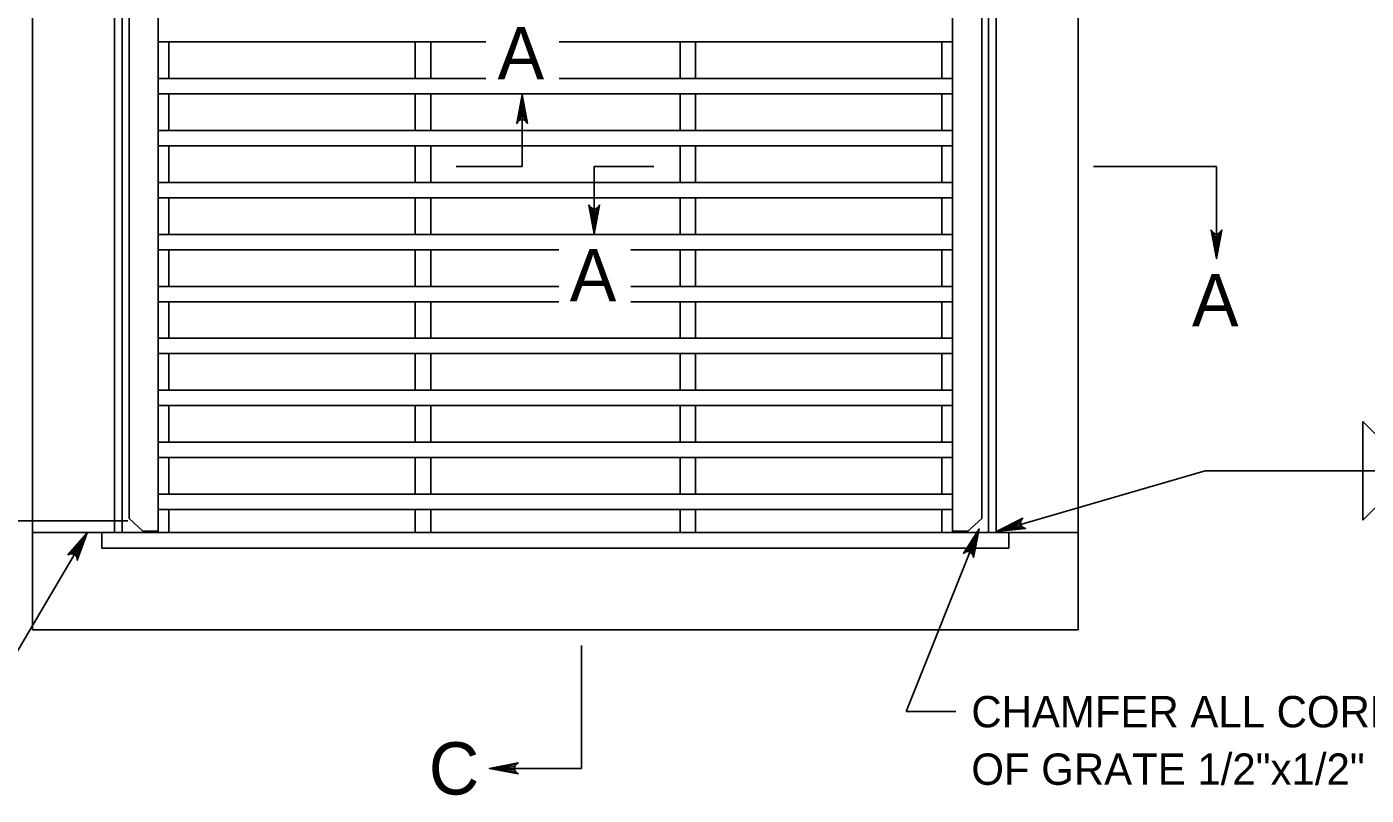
# Model space of a CAD drawing. Extents: x 0.7 to 7.67, y -7.49 to 2.47.
# Drawn here: x 3.543 to 6.105, y -4.567 to -3.097 of the extents above; entities that cross this region are included whole.
import ezdxf

# ---------------------------------------------------------------- set-up
doc = ezdxf.new("R2010")
doc.units = 0
for name, color, linetype in [('DETL-DIMS', 7, 'Continuous'), ('DETL-LINE', 7, 'Continuous'), ('DETL-NOTE', 7, 'Continuous'), ('DETL-TITL', 7, 'Continuous')]:
    doc.layers.add(name, color=color, linetype=linetype)

msp = doc.modelspace()

# ---------------------------------------------------------------- linework, layer by layer
at = {"layer": 'DETL-DIMS'}
for p, q in [((4.4903, -3.3641), (4.4903, -3.2269)), ((4.3644, -3.3641), (4.4903, -3.3641)), ((4.6283, -3.3641), (4.742, -3.3641)), ((4.6283, -3.3641), (4.6283, -3.4929)), ((5.5834, -3.3641), (5.8187, -3.3641)), ((5.8187, -3.3641), (5.8187, -3.5406)), ((5.7972, -3.9466), (5.3981, -4.0624)), ((5.7972, -3.9466), (5.9107, -3.9466)), ((3.7362, -4.0425), (3.0834, -4.0425)), ((3.4216, -4.4666), (3.6583, -4.0653)), ((5.2249, -4.4074), (5.3647, -4.0576)), ((4.6042, -4.2806), (4.6042, -4.5159)), ((5.3202, -4.4074), (5.2249, -4.4074)), ((4.6042, -4.5159), (4.4278, -4.5159))]:
    msp.add_line(p, q, dxfattribs=at)
for points in [[(4.4903, -3.2269), (4.5006, -3.2817), (4.4977, -3.2775), (4.494, -3.2753), (4.4903, -3.2747), (4.4866, -3.2753), (4.4829, -3.2775), (4.48, -3.2817), (4.4903, -3.2269), (4.4829, -3.2775), (4.4866, -3.2753), (4.4903, -3.2269), (4.4903, -3.2747), (4.494, -3.2753), (4.4903, -3.2269), (4.4977, -3.2775)], [(4.6283, -3.4929), (4.6181, -3.438), (4.621, -3.4423), (4.6247, -3.4444), (4.6283, -3.4451), (4.632, -3.4444), (4.6357, -3.4423), (4.6386, -3.438), (4.6283, -3.4929), (4.6357, -3.4423), (4.632, -3.4444), (4.6283, -3.4929), (4.6283, -3.4451), (4.6247, -3.4444), (4.6283, -3.4929), (4.621, -3.4423)], [(5.8187, -3.5406), (5.8084, -3.4858), (5.8113, -3.49), (5.815, -3.4922), (5.8187, -3.4928), (5.8224, -3.4922), (5.826, -3.49), (5.829, -3.4858), (5.8187, -3.5406), (5.826, -3.49), (5.8224, -3.4922), (5.8187, -3.5406), (5.8187, -3.4928), (5.815, -3.4922), (5.8187, -3.5406), (5.8113, -3.49)], [(5.9107, -3.9466), (6.1931, -3.9466), (6.0989, -4.0407), (6.0989, -3.8525), (6.1931, -3.9466), (6.3813, -3.9466)], [(5.3981, -4.0624), (5.4479, -4.0372), (5.4447, -4.0412), (5.4436, -4.0453), (5.444, -4.049), (5.4456, -4.0524), (5.4488, -4.0553), (5.4536, -4.057), (5.3981, -4.0624), (5.4488, -4.0553), (5.4456, -4.0524), (5.3981, -4.0624), (5.444, -4.049), (5.4436, -4.0453), (5.3981, -4.0624), (5.4447, -4.0412)], [(3.6583, -4.0653), (3.6393, -4.1177), (3.6389, -4.1126), (3.6368, -4.1088), (3.634, -4.1064), (3.6305, -4.1051), (3.6262, -4.1051), (3.6215, -4.1073), (3.6583, -4.0653), (3.6262, -4.1051), (3.6305, -4.1051), (3.6583, -4.0653), (3.634, -4.1064), (3.6368, -4.1088), (3.6583, -4.0653), (3.6389, -4.1126)], [(5.3647, -4.0576), (5.3539, -4.1123), (5.3528, -4.1073), (5.3502, -4.1039), (5.347, -4.102), (5.3433, -4.1012), (5.3391, -4.1018), (5.3348, -4.1047), (5.3647, -4.0576), (5.3391, -4.1018), (5.3433, -4.1012), (5.3647, -4.0576), (5.347, -4.102), (5.3502, -4.1039), (5.3647, -4.0576), (5.3528, -4.1073)], [(4.4278, -4.5159), (4.4826, -4.5056), (4.4784, -4.5085), (4.4762, -4.5122), (4.4756, -4.5159), (4.4762, -4.5195), (4.4784, -4.5232), (4.4826, -4.5261), (4.4278, -4.5159), (4.4784, -4.5232), (4.4762, -4.5195), (4.4278, -4.5159), (4.4756, -4.5159), (4.4762, -4.5122), (4.4278, -4.5159), (4.4784, -4.5085)]]:
    msp.add_lwpolyline(points, dxfattribs=at)
at = {"layer": 'DETL-LINE'}
for p, q in [((5.554, -4.2511), (5.554, -2.3688)), ((3.7108, -4.0649), (3.7108, -2.5551)), ((3.7942, -4.0649), (3.7942, -2.5551)), ((5.3138, -4.0649), (5.3138, -2.5551)), ((5.3824, -4.0649), (5.3824, -2.5551)), ((5.3971, -4.0649), (5.3971, -2.5551)), ((5.3697, -4.0381), (5.3697, -2.5818)), ((3.554, -4.2511), (3.554, -2.7585)), ((3.7383, -4.0381), (3.7383, -2.7912)), ((3.7255, -4.0649), (3.7255, -2.7953)), ((3.7942, -3.1258), (4.4212, -3.1258)), ((3.8148, -3.1958), (3.8148, -3.1258)), ((4.286, -3.1258), (4.286, -3.1958)), ((4.3154, -3.1258), (4.3154, -3.1958)), ((4.561, -3.1258), (5.3138, -3.1258)), ((4.7925, -3.1258), (4.7925, -3.1958)), ((4.822, -3.1258), (4.822, -3.1958)), ((5.2932, -3.1958), (5.2932, -3.1258)), ((3.7942, -3.1958), (4.4212, -3.1958)), ((4.561, -3.1958), (5.3138, -3.1958)), ((3.7942, -3.2252), (5.3138, -3.2252)), ((3.8148, -3.2953), (3.8148, -3.2252)), ((4.286, -3.2252), (4.286, -3.2953)), ((4.3154, -3.2252), (4.3154, -3.2953)), ((4.7925, -3.2252), (4.7925, -3.2953)), ((4.822, -3.2252), (4.822, -3.2953)), ((5.2932, -3.2953), (5.2932, -3.2252)), ((3.7942, -3.2953), (5.3138, -3.2953)), ((3.7942, -3.3247), (5.3138, -3.3247)), ((3.8148, -3.3947), (3.8148, -3.3247)), ((4.286, -3.3247), (4.286, -3.3947)), ((4.3154, -3.3247), (4.3154, -3.3947)), ((4.7925, -3.3247), (4.7925, -3.3947)), ((4.822, -3.3247), (4.822, -3.3947)), ((5.2932, -3.3947), (5.2932, -3.3247)), ((3.7942, -3.3947), (5.3138, -3.3947)), ((3.7942, -3.4241), (5.3138, -3.4241)), ((3.8148, -3.4942), (3.8148, -3.4241)), ((4.286, -3.4241), (4.286, -3.4942)), ((4.3154, -3.4241), (4.3154, -3.4942)), ((4.7925, -3.4241), (4.7925, -3.4942)), ((4.822, -3.4241), (4.822, -3.4942)), ((5.2932, -3.4942), (5.2932, -3.4241)), ((3.7942, -3.4942), (5.3138, -3.4942)), ((3.7942, -3.5236), (4.5603, -3.5236)), ((3.8148, -3.5936), (3.8148, -3.5236)), ((4.286, -3.5236), (4.286, -3.5936)), ((4.3154, -3.5236), (4.3154, -3.5936)), ((4.698, -3.5236), (5.3138, -3.5236)), ((4.7925, -3.5236), (4.7925, -3.5936)), ((4.822, -3.5236), (4.822, -3.5936)), ((5.2932, -3.5936), (5.2932, -3.5236)), ((3.7942, -3.5936), (4.5603, -3.5936)), ((4.698, -3.5936), (5.3138, -3.5936)), ((3.7942, -3.623), (4.5603, -3.623)), ((3.8148, -3.693), (3.8148, -3.623)), ((4.286, -3.623), (4.286, -3.693)), ((4.3154, -3.623), (4.3154, -3.693)), ((4.698, -3.623), (5.3138, -3.623)), ((4.7925, -3.623), (4.7925, -3.693)), ((4.822, -3.623), (4.822, -3.693)), ((5.2932, -3.693), (5.2932, -3.623)), ((3.7942, -3.693), (5.3138, -3.693)), ((3.7942, -3.7224), (5.3138, -3.7224)), ((3.8148, -3.7925), (3.8148, -3.7224)), ((4.286, -3.7224), (4.286, -3.7925)), ((4.3154, -3.7224), (4.3154, -3.7925)), ((4.7925, -3.7224), (4.7925, -3.7925)), ((4.822, -3.7224), (4.822, -3.7925)), ((5.2932, -3.7925), (5.2932, -3.7224)), ((3.7942, -3.7925), (5.3138, -3.7925)), ((3.7942, -3.8219), (5.3138, -3.8219)), ((3.8148, -3.8919), (3.8148, -3.8219)), ((4.286, -3.8219), (4.286, -3.8919)), ((4.3154, -3.8219), (4.3154, -3.8919)), ((4.7925, -3.8219), (4.7925, -3.8919)), ((4.822, -3.8219), (4.822, -3.8919)), ((5.2932, -3.8919), (5.2932, -3.8219)), ((3.7942, -3.8919), (5.3138, -3.8919)), ((3.7942, -3.9213), (5.3138, -3.9213)), ((3.8148, -3.9913), (3.8148, -3.9213)), ((4.286, -3.9213), (4.286, -3.9913)), ((4.3154, -3.9213), (4.3154, -3.9913)), ((4.7925, -3.9213), (4.7925, -3.9913)), ((4.822, -3.9213), (4.822, -3.9913)), ((5.2932, -3.9913), (5.2932, -3.9213)), ((3.7942, -3.9913), (5.3138, -3.9913)), ((3.7942, -4.0208), (5.3138, -4.0208)), ((3.8148, -4.0649), (3.8148, -4.0208)), ((4.286, -4.0208), (4.286, -4.0649)), ((4.3154, -4.0208), (4.3154, -4.0649)), ((4.7925, -4.0208), (4.7925, -4.0649)), ((4.822, -4.0208), (4.822, -4.0649)), ((5.2932, -4.0649), (5.2932, -4.0208)), ((3.7383, -4.0381), (3.7648, -4.062)), ((5.3697, -4.0381), (5.3432, -4.0623)), ((3.554, -4.0649), (5.554, -4.0649)), ((3.6863, -4.0943), (3.6863, -4.0649)), ((3.7648, -4.062), (3.7942, -4.062)), ((5.3138, -4.0623), (5.3432, -4.0623)), ((5.4216, -4.0943), (5.4216, -4.0649)), ((3.6863, -4.0943), (5.4216, -4.0943)), ((3.554, -4.2511), (5.554, -4.2511))]:
    msp.add_line(p, q, dxfattribs=at)

# ---------------------------------------------------------------- texts
at = {"layer": 'DETL-NOTE'}
for s, p in [('CHAMFER ALL CORNERS', (5.3497, -4.4374)), ('OF GRATE 1/2"x1/2"', (5.3497, -4.5474))]:
    msp.add_text(s, height=0.06, dxfattribs=at).set_placement(p)
at = {"layer": 'DETL-TITL'}
for s, p in [('A', (4.4433, -3.1975)), ('A', (4.5814, -3.6223)), ('A', (5.7717, -3.67)), ('C', (4.3118, -4.5659))]:
    msp.add_text(s, height=0.1, dxfattribs=at).set_placement(p)

doc.saveas('drawing.dxf')
